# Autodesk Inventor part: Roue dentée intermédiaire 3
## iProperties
Author: Flavien MARTY
Shininess: 41.0
PropertySet Name: _Private Model Information
Created: 2001-10
Part Number: Roue dentée intermédiaire 3
Material: Par défaut
Document SubType Name: Modélisation
Designer: Flavien MARTY
Control State: 0
Master: False
Checked Out: False
PropertySet Name: Design Tracking Control
Density: 0.0
Volumn: 0.0
Area: 0.0
PropertySet Name: Model Information
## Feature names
1. Base1
